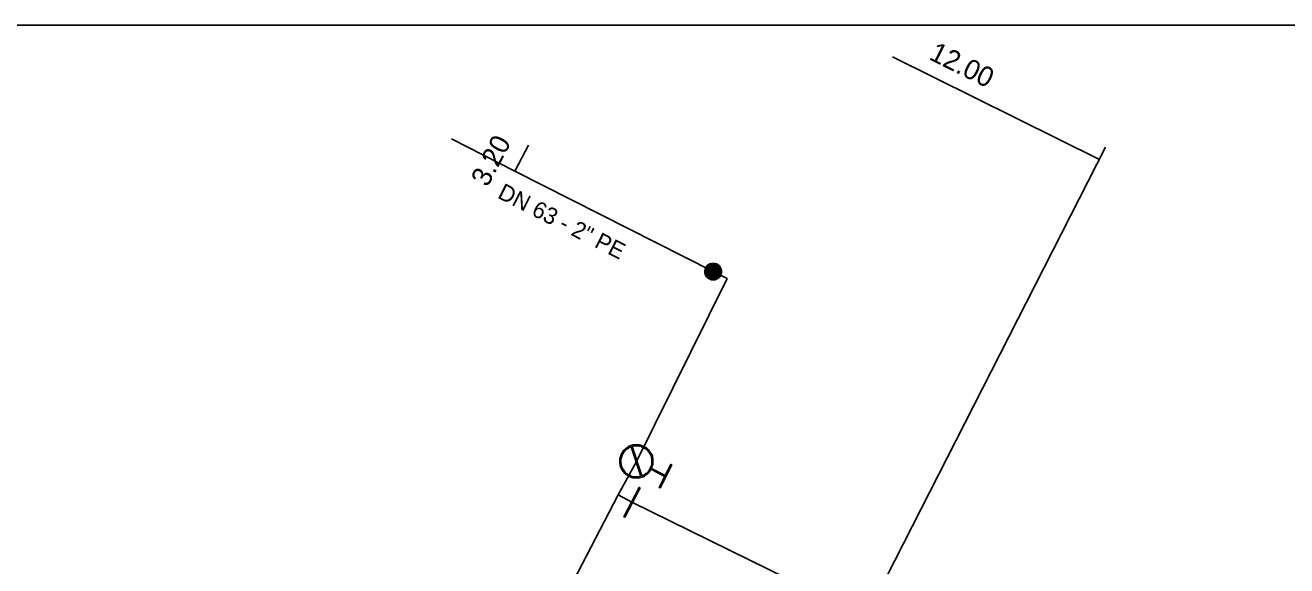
# Model space of a CAD drawing. Extents: x -820257 to -819974, y -1070894 to -1070484.
# Drawn here: x -820185.5 to -820109.2, y -1070517.1 to -1070484.4 of the extents above; entities that cross this region are included whole.
import ezdxf

# ---------------------------------------------------------------- set-up
doc = ezdxf.new("R2010")
doc.units = 0
for name, color, linetype in [('Default', 7, 'Continuous'), ('Hydrant', 7, 'Continuous'), ('Oměrka vodovodu', 7, 'Continuous'), ('Oměrka-text', 7, 'Continuous'), ('Přípojka vodovodu', 7, 'Continuous'), ('Přípojka-popis', 7, 'Continuous'), ('Přípojkový uzávěr', 7, 'Continuous'), ('Roz-řad', 7, 'Continuous'), ('Řad-šoupě', 7, 'Continuous')]:
    doc.layers.add(name, color=color, linetype=linetype)

msp = doc.modelspace()

# ---------------------------------------------------------------- linework, layer by layer
at = {"layer": 'Default'}
msp.add_lwpolyline([(-819975.603, -1070484.403), (-820256.81, -1070484.403), (-820256.81, -1070893.932)], dxfattribs=at)
at = {"layer": 'Hydrant'}
for points in [[(-820148.265, -1070511.685), (-820148.849, -1070509.898)], [(-820148.789, -1070509.88), (-820148.207, -1070511.666)], [(-820147.622, -1070511.208), (-820146.786, -1070511.633), (-820146.446, -1070510.964), (-820146.39, -1070510.993), (-820147.099, -1070512.385), (-820147.154, -1070512.357), (-820146.814, -1070511.689), (-820147.65, -1070511.264)]]:
    msp.add_lwpolyline(points, dxfattribs=at)
for points in [[(-820147.65, -1070511.264), (-820147.764, -1070511.471), (-820147.974, -1070511.616), (-820148.197, -1070511.77), (-820148.472, -1070511.781), (-820148.747, -1070511.792), (-820148.981, -1070511.674), (-820149.212, -1070511.556), (-820149.365, -1070511.33), (-820149.517, -1070511.105), (-820149.527, -1070510.833), (-820149.536, -1070510.561), (-820149.419, -1070510.329), (-820149.301, -1070510.098), (-820149.075, -1070509.945), (-820148.85, -1070509.792), (-820148.578, -1070509.783), (-820148.305, -1070509.773), (-820148.074, -1070509.891), (-820147.841, -1070510.01), (-820147.688, -1070510.239), (-820147.535, -1070510.468), (-820147.528, -1070510.739), (-820147.521, -1070510.992), (-820147.622, -1070511.208)], [(-820148.849, -1070509.898), (-820148.949, -1070509.935), (-820149.04, -1070509.998), (-820149.252, -1070510.14), (-820149.363, -1070510.357), (-820149.474, -1070510.575), (-820149.464, -1070510.831), (-820149.455, -1070511.086), (-820149.313, -1070511.297), (-820149.17, -1070511.507), (-820148.952, -1070511.618), (-820148.733, -1070511.73), (-820148.475, -1070511.718), (-820148.365, -1070511.713), (-820148.265, -1070511.685)], [(-820148.207, -1070511.666), (-820148.102, -1070511.627), (-820148.008, -1070511.563), (-820147.799, -1070511.418), (-820147.692, -1070511.207), (-820147.584, -1070510.997), (-820147.591, -1070510.742), (-820147.597, -1070510.487), (-820147.74, -1070510.272), (-820147.883, -1070510.058), (-820148.102, -1070509.947), (-820148.32, -1070509.836), (-820148.575, -1070509.847), (-820148.686, -1070509.849), (-820148.789, -1070509.88)]]:
    msp.add_open_spline(points, degree=3, dxfattribs=at)
at = {"layer": 'Oměrka vodovodu'}
for p, q in [((-820133.036, -1070486.323), (-820120.524, -1070492.522)), ((-820155.871, -1070493.228), (-820155.044, -1070491.663))]:
    msp.add_line(p, q, dxfattribs=at)
at = {"layer": 'Přípojka vodovodu'}
for points in [[(-820143.043, -1070499.732), (-820143.884, -1070499.306), (-820155.871, -1070493.228), (-820159.716, -1070491.278)], [(-820134.64, -1070520.216), (-820133.959, -1070518.88), (-820120.148, -1070491.785)]]:
    msp.add_lwpolyline(points, dxfattribs=at)
at = {"layer": 'Přípojkový uzávěr'}
for points in [[(-820143.884, -1070498.806), (-820143.759, -1070498.806), (-820143.639, -1070498.87), (-820143.519, -1070498.935), (-820143.452, -1070499.055), (-820143.384, -1070499.176), (-820143.384, -1070499.306), (-820143.384, -1070499.436), (-820143.45, -1070499.555), (-820143.516, -1070499.674), (-820143.635, -1070499.74), (-820143.754, -1070499.806), (-820143.884, -1070499.806), (-820144.014, -1070499.806), (-820144.133, -1070499.74), (-820144.252, -1070499.674), (-820144.318, -1070499.555), (-820144.384, -1070499.436), (-820144.384, -1070499.306), (-820144.384, -1070499.176), (-820144.317, -1070499.055), (-820144.25, -1070498.935), (-820144.13, -1070498.87), (-820144.011, -1070498.806), (-820143.884, -1070498.806)], [(-820143.884, -1070498.853), (-820143.999, -1070498.853), (-820144.107, -1070498.911), (-820144.216, -1070498.97), (-820144.276, -1070499.079), (-820144.337, -1070499.188), (-820144.337, -1070499.306), (-820144.337, -1070499.424), (-820144.278, -1070499.532), (-820144.218, -1070499.639), (-820144.11, -1070499.699), (-820144.002, -1070499.759), (-820143.884, -1070499.759), (-820143.766, -1070499.759), (-820143.658, -1070499.699), (-820143.55, -1070499.639), (-820143.49, -1070499.532), (-820143.431, -1070499.424), (-820143.431, -1070499.306), (-820143.431, -1070499.188), (-820143.492, -1070499.079), (-820143.554, -1070498.97), (-820143.662, -1070498.911), (-820143.77, -1070498.853), (-820143.884, -1070498.853)], [(-820143.884, -1070498.887), (-820143.779, -1070498.887), (-820143.679, -1070498.941), (-820143.579, -1070498.995), (-820143.522, -1070499.096), (-820143.465, -1070499.197), (-820143.465, -1070499.306), (-820143.465, -1070499.415), (-820143.52, -1070499.515), (-820143.575, -1070499.615), (-820143.675, -1070499.67), (-820143.775, -1070499.725), (-820143.884, -1070499.725), (-820143.993, -1070499.725), (-820144.093, -1070499.67), (-820144.193, -1070499.615), (-820144.248, -1070499.515), (-820144.303, -1070499.415), (-820144.303, -1070499.306), (-820144.303, -1070499.197), (-820144.247, -1070499.096), (-820144.191, -1070498.995), (-820144.09, -1070498.941), (-820143.99, -1070498.887), (-820143.884, -1070498.887)], [(-820143.885, -1070498.931), (-820144.041, -1070498.931), (-820144.15, -1070499.041), (-820144.259, -1070499.151), (-820144.259, -1070499.306), (-820144.259, -1070499.462), (-820144.149, -1070499.571), (-820144.039, -1070499.681), (-820143.885, -1070499.681), (-820143.729, -1070499.681), (-820143.619, -1070499.571), (-820143.509, -1070499.462), (-820143.509, -1070499.306), (-820143.509, -1070499.151), (-820143.618, -1070499.041), (-820143.727, -1070498.931), (-820143.885, -1070498.931)], [(-820143.885, -1070498.977), (-820143.748, -1070498.977), (-820143.652, -1070499.073), (-820143.557, -1070499.169), (-820143.557, -1070499.305), (-820143.557, -1070499.441), (-820143.653, -1070499.537), (-820143.749, -1070499.633), (-820143.885, -1070499.633), (-820144.022, -1070499.633), (-820144.117, -1070499.537), (-820144.213, -1070499.441), (-820144.213, -1070499.305), (-820144.213, -1070499.169), (-820144.117, -1070499.073), (-820144.022, -1070498.977), (-820143.885, -1070498.977)], [(-820143.885, -1070499.016), (-820144.005, -1070499.016), (-820144.089, -1070499.101), (-820144.174, -1070499.185), (-820144.174, -1070499.305), (-820144.174, -1070499.425), (-820144.089, -1070499.509), (-820144.005, -1070499.594), (-820143.885, -1070499.594), (-820143.765, -1070499.594), (-820143.681, -1070499.509), (-820143.596, -1070499.425), (-820143.596, -1070499.305), (-820143.596, -1070499.185), (-820143.68, -1070499.101), (-820143.764, -1070499.016), (-820143.885, -1070499.016)], [(-820143.884, -1070499.056), (-820143.78, -1070499.056), (-820143.707, -1070499.129), (-820143.634, -1070499.202), (-820143.634, -1070499.306), (-820143.634, -1070499.41), (-820143.707, -1070499.483), (-820143.78, -1070499.556), (-820143.884, -1070499.556), (-820143.988, -1070499.556), (-820144.061, -1070499.483), (-820144.134, -1070499.41), (-820144.134, -1070499.306), (-820144.134, -1070499.202), (-820144.061, -1070499.129), (-820143.989, -1070499.056), (-820143.884, -1070499.056)], [(-820143.884, -1070499.102), (-820143.969, -1070499.102), (-820144.028, -1070499.162), (-820144.088, -1070499.221), (-820144.088, -1070499.306), (-820144.088, -1070499.39), (-820144.028, -1070499.449), (-820143.969, -1070499.509), (-820143.884, -1070499.509), (-820143.801, -1070499.509), (-820143.741, -1070499.449), (-820143.681, -1070499.39), (-820143.681, -1070499.306), (-820143.681, -1070499.221), (-820143.741, -1070499.162), (-820143.8, -1070499.102), (-820143.884, -1070499.102)], [(-820143.884, -1070499.137), (-820143.814, -1070499.137), (-820143.765, -1070499.186), (-820143.716, -1070499.235), (-820143.716, -1070499.306), (-820143.716, -1070499.376), (-820143.765, -1070499.425), (-820143.815, -1070499.474), (-820143.884, -1070499.474), (-820143.955, -1070499.474), (-820144.004, -1070499.425), (-820144.053, -1070499.376), (-820144.053, -1070499.306), (-820144.053, -1070499.235), (-820144.004, -1070499.186), (-820143.955, -1070499.137), (-820143.884, -1070499.137)], [(-820143.884, -1070499.181), (-820143.936, -1070499.181), (-820143.973, -1070499.218), (-820144.009, -1070499.254), (-820144.009, -1070499.306), (-820144.009, -1070499.358), (-820143.972, -1070499.394), (-820143.936, -1070499.431), (-820143.884, -1070499.431), (-820143.832, -1070499.431), (-820143.796, -1070499.394), (-820143.759, -1070499.358), (-820143.759, -1070499.306), (-820143.759, -1070499.254), (-820143.795, -1070499.218), (-820143.832, -1070499.181), (-820143.884, -1070499.181)], [(-820143.884, -1070499.228), (-820143.851, -1070499.228), (-820143.829, -1070499.25), (-820143.806, -1070499.273), (-820143.806, -1070499.306), (-820143.806, -1070499.338), (-820143.829, -1070499.361), (-820143.851, -1070499.384), (-820143.884, -1070499.384), (-820143.917, -1070499.384), (-820143.94, -1070499.361), (-820143.963, -1070499.338), (-820143.963, -1070499.306), (-820143.963, -1070499.273), (-820143.94, -1070499.25), (-820143.917, -1070499.228), (-820143.884, -1070499.228)], [(-820143.884, -1070499.259), (-820143.904, -1070499.259), (-820143.918, -1070499.273), (-820143.931, -1070499.286), (-820143.931, -1070499.306), (-820143.931, -1070499.326), (-820143.918, -1070499.339), (-820143.904, -1070499.353), (-820143.884, -1070499.353), (-820143.864, -1070499.353), (-820143.851, -1070499.339), (-820143.838, -1070499.326), (-820143.838, -1070499.306), (-820143.838, -1070499.286), (-820143.851, -1070499.273), (-820143.864, -1070499.259), (-820143.884, -1070499.259)]]:
    msp.add_open_spline(points, degree=3, dxfattribs=at)
at = {"layer": 'Roz-řad'}
for p, q in [((-820143.043, -1070499.732), (-820148.527, -1070510.782)), ((-820148.527, -1070510.782), (-820149.629, -1070512.816)), ((-820149.629, -1070512.816), (-820148.797, -1070513.257))]:
    msp.add_line(p, q, dxfattribs=at)
for points in [[(-820149.629, -1070512.816), (-820182.322, -1070575.745), (-820181.435, -1070576.285)], [(-820148.797, -1070513.257), (-820134.64, -1070520.216), (-820133.832, -1070520.633), (-820116.57, -1070529.663)]]:
    msp.add_lwpolyline(points, dxfattribs=at)
at = {"layer": 'Řad-šoupě'}
msp.add_lwpolyline([(-820148.306, -1070512.385), (-820149.232, -1070514.158), (-820149.287, -1070514.129), (-820148.362, -1070512.356), (-820148.306, -1070512.385)], dxfattribs=at)

# ---------------------------------------------------------------- texts
at = {"layer": 'Oměrka-text'}
for s, rotation, p in [('12.00', 333.64415, (-820130.889, -1070486.439)), (' 3.20', 62.1465, (-820157.743, -1070494.633))]:
    msp.add_text(s, height=1.2, rotation=rotation, dxfattribs=at).set_placement(p)
at = {"layer": 'Přípojka-popis'}
msp.add_text('DN 63 - 2" PE', height=1, rotation=333.11273, dxfattribs=at).set_placement((-820156.986, -1070494.821))

doc.saveas('drawing.dxf')
